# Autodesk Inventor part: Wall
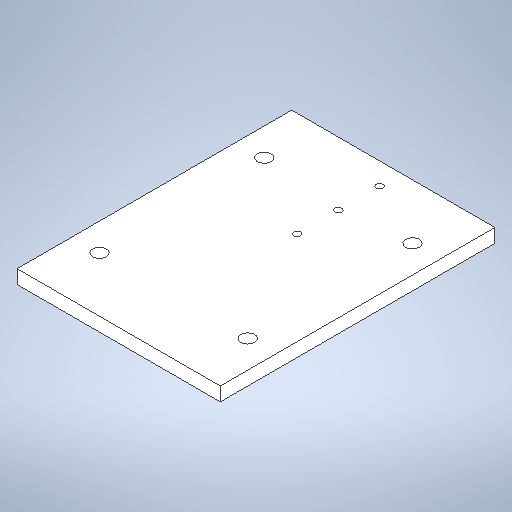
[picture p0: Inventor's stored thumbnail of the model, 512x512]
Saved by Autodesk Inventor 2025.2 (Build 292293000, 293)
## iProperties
Created: 2025-09
Part Number: Wall
Material: Generic
Document SubType Name: Modeling
Designer: tyler
Density: 1 g/cm^3
Appearance: Default
Author: tyler
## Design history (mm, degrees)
sketch "Sketch1"
  geometry: L1 (-46.99, -63.5)-(46.99, -63.5); L2 (46.99, -63.5)-(46.99, 63.5); L3 (46.99, 63.5)-(-46.99, 63.5); L4 (-46.99, 63.5)-(-46.99, -63.5); L5 (-46.99, -63.5)-(46.99, 63.5); L6 (46.99, -63.5)-(-46.99, 63.5); 1 further point
  constraints: 12 end point, 2 midpoint, 2 parallel, 1 horizontal, 1 perpendicular
  dimensions: "d0" = 93.98 distance of L3.end L2.end; "d1" = 127 distance of L2.end L1.end
extrude "Extrusion1" new body sketch "Sketch1" distance "d2" = 6.35; taper "d3" = 0 deg
sketch "Sketch2"
  geometry: L1 (-46.99, -63.5)-(46.99, -63.5) reference; L2 (46.99, -63.5)-(46.99, -38.1); L3 (46.99, -63.5)-(46.99, 63.5) reference; L4 (46.99, -38.1)-(34.29, -38.1); L5 (46.99, 63.5)-(46.99, 38.1); L6 (46.99, 38.1)-(34.29, 38.1); L7 (0, -63.5)-(0, -54.705); L8 (-46.99, 63.5)-(-46.99, -63.5) reference; C1 r 3.175 at (34.29, -38.1); C2 r 3.175 at (34.29, 38.1); C3 r 3.175 at (-34.29, -38.1); C4 r 3.175 at (-34.29, 38.1); 1 further point
  constraints: 10 end point, 4 centre point, 2 coincident, 2 perpendicular, 2 point on line, 2 symmetric about line, 1 midpoint, 1 vertical, 2 other
  dimensions: "d4" = 25.4 distance of L1.end L2.end; "d5" = 12.7 distance of L2.end L4.end; "d6" = 25.4 distance of L3.end L5.end; "d7" = 12.7 distance of L5.end L6.end; "d8" = 6.35 diameter of C1; "d9" = 6.35 diameter of C2; "d21" = 12.7 distance from line of L8 C3.centre (derived)
extrude "Extrusion2" cut sketch "Sketch2" distance "d10" = 6.35; taper "d11" = 0 deg
sketch "Sketch3"
  geometry: L1 (3.81, 15.24)-(3.81, 34.29); L2 (3.81, 34.29)-(3.81, 53.34); L3 (46.99, -63.5)-(46.99, 63.5) reference; C1 r 1.587 at (3.81, 15.24); C2 r 1.587 at (3.81, 34.29); C3 r 1.587 at (3.81, 53.34); 1 further point
  constraints: 4 end point, 3 centre point, 3 coincident, 1 vertical
  dimensions: "d14" = 19.05 distance of L1.start L1.end; "d15" = 19.05 distance of L1.end L2.end; "d16" = 3.175 diameter of C1; "d17" = 3.175 diameter of C2; "d18" = 3.175 diameter of C3; "d25" = 43.18 distance between parallel lines of L1 L3
extrude "Extrusion3" cut sketch "Sketch3" distance "d19" = 6.35; taper "d20" = 0 deg
body "Solid1"
